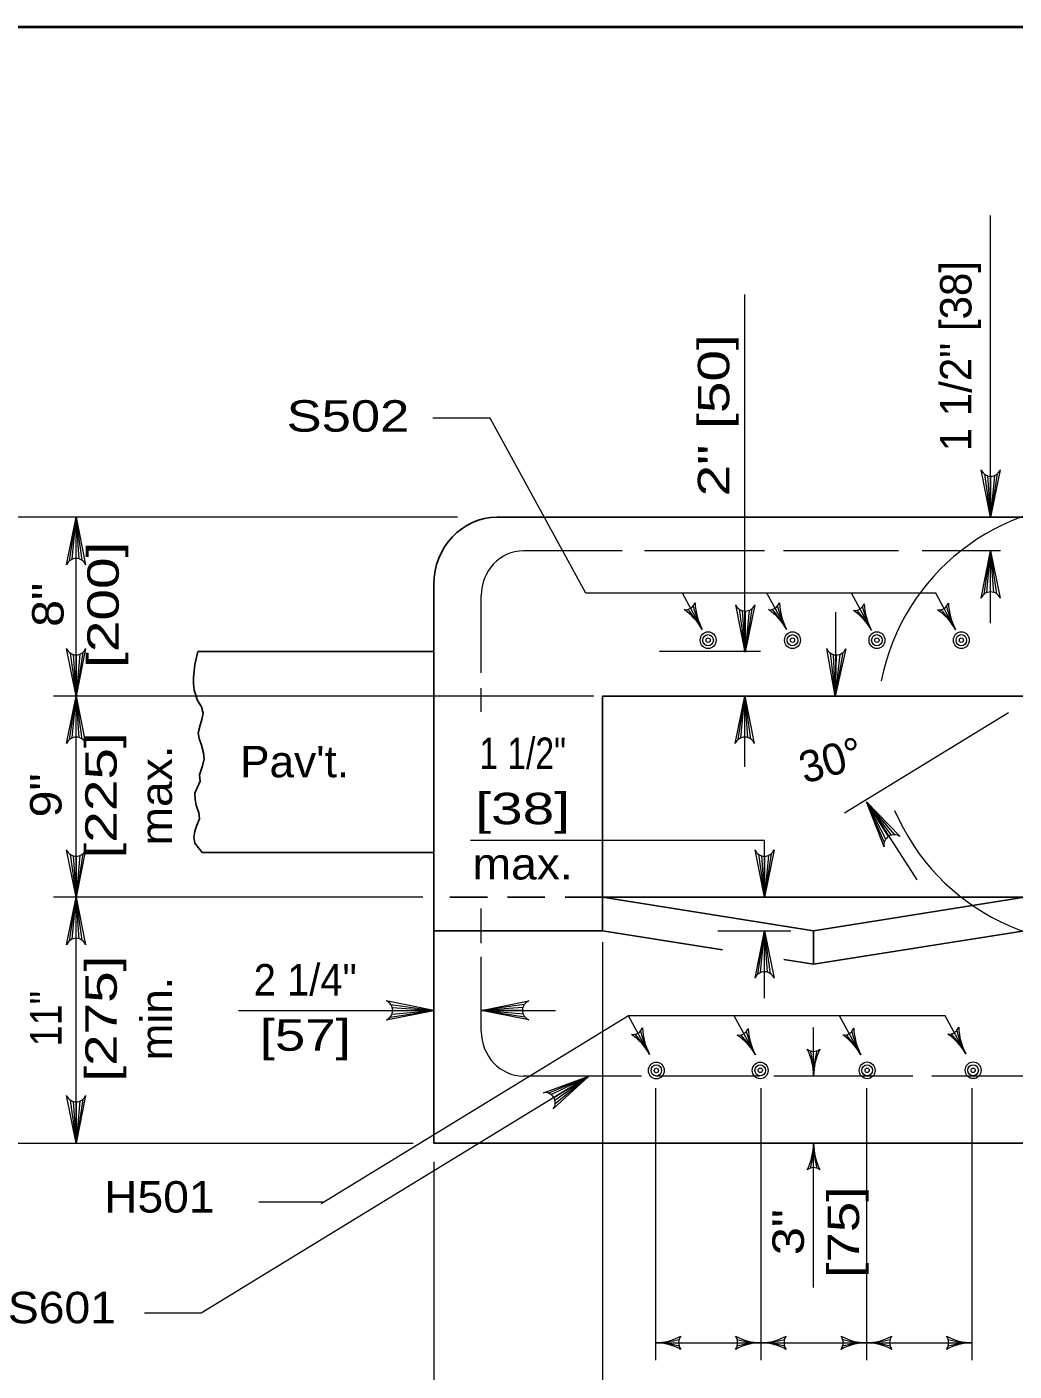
# Model space of a CAD drawing. Extents: x 339.1 to 373.1, y 1412.7 to 1456.7.
# Drawn here: x 355.85 to 360.75, y 1427.58 to 1434.25 of the extents above; entities that cross this region are included whole.
import ezdxf
from ezdxf.enums import TextEntityAlignment as Align

# ---------------------------------------------------------------- set-up
doc = ezdxf.new("R2010")
doc.units = 0
doc.header["$LTSCALE"] = 0.062
doc.linetypes.add('MEDIUM_DASHED', pattern=[4.5, 3, -1.5])
doc.layers.add('1', color=7, linetype='Continuous', lineweight=13)

msp = doc.modelspace()

# ---------------------------------------------------------------- linework, layer by layer
at = {"layer": '1', "lineweight": 25}
for p, q in [((341.0605, 1434.2455), (372.5605, 1434.2455)), ((361.21592, 1431.81325), (358.1795, 1431.81325)), ((357.86533, 1431.14808), (356.69433, 1431.14808)), ((360.85292, 1430.92642), (358.703, 1430.92642)), ((358.703, 1430.92642), (358.703, 1429.98042)), ((357.86533, 1430.15042), (356.71642, 1430.15042)), ((358.703, 1429.98042), (358.703, 1429.76242)), ((358.703, 1429.76242), (357.865, 1429.76242)), ((359.29867, 1429.66783), (358.703, 1429.76242)), ((360.79708, 1429.76242), (359.75008, 1429.59617)), ((359.75008, 1429.59617), (359.75008, 1429.76242)), ((359.75008, 1429.59617), (359.60167, 1429.61975)), ((357.86533, 1428.70933), (361.63475, 1428.70933))]:
    msp.add_line(p, q, dxfattribs=at)
at = {"layer": '1'}
for p, q in [((360.62858, 1431.81325), (360.62858, 1433.30925)), ((359.4085, 1431.14733), (359.4085, 1432.91817)), ((360.59875, 1432.0265), (360.62858, 1431.81325)), ((360.6135, 1432.01925), (360.62858, 1431.81325)), ((360.66158, 1432.029), (360.62858, 1431.81325)), ((360.64775, 1432.02083), (360.62858, 1431.81325)), ((360.62858, 1432.01708), (360.62858, 1431.81325)), ((357.98283, 1431.81325), (355.29933, 1431.81325)), ((356.05758, 1431.59742), (356.09058, 1431.81325)), ((356.07142, 1431.60558), (356.09058, 1431.81325)), ((356.09058, 1431.11825), (356.09058, 1431.81325)), ((356.09058, 1431.60933), (356.09058, 1431.81325)), ((356.10567, 1431.60717), (356.09058, 1431.81325)), ((356.12042, 1431.59992), (356.09058, 1431.81325)), ((358.80058, 1431.64692), (358.31033, 1431.64692)), ((359.5055, 1431.64692), (358.9115, 1431.64692)), ((360.17075, 1431.64692), (359.6005, 1431.64692)), ((360.67767, 1431.64692), (360.2895, 1431.64692)), ((360.59567, 1431.43117), (360.62858, 1431.64692)), ((360.60942, 1431.43933), (360.62858, 1431.64692)), ((360.62858, 1431.28825), (360.62858, 1431.64692)), ((360.62858, 1431.44308), (360.62858, 1431.64692)), ((360.64367, 1431.44092), (360.62858, 1431.64692)), ((360.65842, 1431.43367), (360.62858, 1431.64692)), ((358.10092, 1431.04183), (358.10092, 1431.42525)), ((359.1975, 1431.25675), (359.09958, 1431.43617)), ((359.61633, 1431.25675), (359.51842, 1431.43617)), ((360.03733, 1431.25275), (359.93725, 1431.43617)), ((359.381, 1431.35733), (359.41083, 1431.14408)), ((359.39575, 1431.35017), (359.41083, 1431.14408)), ((359.44383, 1431.35992), (359.41083, 1431.14408)), ((359.43, 1431.35175), (359.41083, 1431.14408)), ((359.41083, 1431.34792), (359.41083, 1431.14408)), ((359.86108, 1430.94608), (359.86108, 1431.34225)), ((356.06075, 1431.13967), (356.09058, 1430.92642)), ((356.0755, 1431.13242), (356.09058, 1430.92642)), ((356.12358, 1431.14217), (356.09058, 1430.92642)), ((356.10975, 1431.134), (356.09058, 1430.92642)), ((356.09058, 1431.13025), (356.09058, 1430.92642)), ((358.98533, 1431.14833), (359.48592, 1431.14833)), ((359.83192, 1431.14042), (359.85775, 1430.92658)), ((359.8465, 1431.13292), (359.85775, 1430.92658)), ((359.89475, 1431.14175), (359.85775, 1430.92658)), ((359.88075, 1431.13383), (359.85775, 1430.92658)), ((359.8615, 1431.13042), (359.85775, 1430.92658)), ((358.65983, 1430.92642), (355.9785, 1430.92642)), ((356.05758, 1430.71058), (356.09058, 1430.92642)), ((356.07142, 1430.71875), (356.09058, 1430.92642)), ((356.09058, 1430.7225), (356.09058, 1430.92642)), ((356.10567, 1430.72033), (356.09058, 1430.92642)), ((356.12042, 1430.71308), (356.09058, 1430.92642)), ((358.10092, 1430.84767), (358.10092, 1430.96633)), ((359.3755, 1430.71058), (359.4085, 1430.92642)), ((359.38933, 1430.71875), (359.4085, 1430.92642)), ((359.4085, 1430.57492), (359.4085, 1430.92642)), ((359.4085, 1430.7225), (359.4085, 1430.92642)), ((359.42358, 1430.72033), (359.4085, 1430.92642)), ((359.43833, 1430.71308), (359.4085, 1430.92642)), ((360.71733, 1430.8435), (359.90292, 1430.34567)), ((360.12233, 1430.23067), (360.01267, 1430.4025)), ((360.10817, 1430.21717), (360.01267, 1430.4025)), ((360.10092, 1430.20283), (360.01267, 1430.4025)), ((360.13625, 1430.23692), (360.01267, 1430.4025)), ((360.15258, 1430.23875), (360.01267, 1430.4025)), ((360.016, 1430.399), (360.262, 1430.0155)), ((359.276, 1430.20975), (358.04725, 1430.20975)), ((359.50642, 1430.20975), (359.276, 1430.20975)), ((359.50642, 1429.92875), (359.50642, 1430.20975)), ((356.06075, 1430.142), (356.09058, 1429.92875)), ((356.0755, 1430.13475), (356.09058, 1429.92875)), ((356.12358, 1430.1445), (356.09058, 1429.92875)), ((356.10975, 1430.13633), (356.09058, 1429.92875)), ((356.09058, 1430.13258), (356.09058, 1429.92875)), ((359.47658, 1430.142), (359.50642, 1429.92875)), ((359.49133, 1430.13475), (359.50642, 1429.92875)), ((359.53942, 1430.1445), (359.50642, 1429.92875)), ((359.52558, 1430.13633), (359.50642, 1429.92875)), ((359.50642, 1430.13258), (359.50642, 1429.92875)), ((357.81142, 1429.92875), (355.9785, 1429.92875)), ((356.05758, 1429.71292), (356.09058, 1429.92875)), ((356.07142, 1429.72108), (356.09058, 1429.92875)), ((356.09058, 1429.72483), (356.09058, 1429.92875)), ((356.10567, 1429.72267), (356.09058, 1429.92875)), ((356.12042, 1429.71542), (356.09058, 1429.92875)), ((358.10092, 1429.70025), (358.10092, 1429.872)), ((359.27425, 1429.76242), (359.63642, 1429.76242)), ((359.47342, 1429.54667), (359.50642, 1429.76242)), ((359.48725, 1429.55483), (359.50642, 1429.76242)), ((359.50642, 1429.42783), (359.50642, 1429.76242)), ((359.50642, 1429.55858), (359.50642, 1429.76242)), ((359.5215, 1429.55633), (359.50642, 1429.76242)), ((359.53625, 1429.54917), (359.50642, 1429.76242)), ((358.703, 1429.706), (358.703, 1427.18717)), ((358.10092, 1429.26358), (358.10092, 1429.63308)), ((357.65208, 1429.39733), (357.86533, 1429.3675)), ((358.31425, 1429.39733), (358.10092, 1429.3675)), ((356.89608, 1429.3675), (357.86533, 1429.3675)), ((357.64958, 1429.3345), (357.86533, 1429.3675)), ((357.65775, 1429.34833), (357.86533, 1429.3675)), ((357.65925, 1429.38258), (357.86533, 1429.3675)), ((357.6615, 1429.3675), (357.86533, 1429.3675)), ((358.307, 1429.38258), (358.10092, 1429.3675)), ((358.10092, 1429.3675), (358.47, 1429.3675)), ((358.30483, 1429.3675), (358.10092, 1429.3675)), ((358.30858, 1429.34833), (358.10092, 1429.3675)), ((358.31675, 1429.3345), (358.10092, 1429.3675)), ((358.93642, 1429.14942), (358.83217, 1429.34033)), ((359.4615, 1429.14642), (359.35575, 1429.34033)), ((359.98483, 1429.14675), (359.87925, 1429.34033)), ((360.50567, 1429.1515), (360.40275, 1429.34033)), ((359.75008, 1429.04192), (359.75008, 1429.28233)), ((358.6345, 1429.04192), (356.71133, 1427.86642)), ((358.89567, 1429.04192), (358.31033, 1429.04192)), ((358.43317, 1428.9575), (358.6345, 1429.04192)), ((358.44733, 1428.95), (358.6345, 1429.04192)), ((358.46058, 1428.93558), (358.6345, 1429.04192)), ((358.46658, 1428.92158), (358.6345, 1429.04192)), ((358.46808, 1428.90517), (358.6345, 1429.04192)), ((359.48167, 1429.04192), (358.96683, 1429.04192)), ((360.24208, 1429.04192), (359.553, 1429.04192)), ((360.86767, 1429.04192), (360.337, 1429.04192)), ((356.06075, 1428.92258), (356.09058, 1428.70933)), ((356.12358, 1428.92517), (356.09058, 1428.70933)), ((358.96475, 1428.98133), (358.96475, 1427.63217)), ((359.48825, 1428.98133), (359.48825, 1427.63217)), ((360.01183, 1428.98133), (360.01183, 1427.63217)), ((360.53533, 1428.98133), (360.53533, 1427.63217)), ((356.0755, 1428.91542), (356.09058, 1428.70933)), ((356.10975, 1428.917), (356.09058, 1428.70933)), ((356.09058, 1428.91317), (356.09058, 1428.70933)), ((355.29933, 1428.70933), (357.76242, 1428.70933)), ((359.75008, 1427.99358), (359.75008, 1428.70933)), ((357.86533, 1428.61708), (357.86533, 1426.47592)), ((357.31917, 1428.41558), (356.99667, 1428.41558)), ((356.71133, 1427.86642), (356.42958, 1427.86642))]:
    msp.add_line(p, q, dxfattribs=at)
at = {"layer": '1', "linetype": 'MEDIUM_DASHED', "lineweight": 25}
msp.add_line((358.703, 1429.92875), (357.86542, 1429.92875), dxfattribs=at)
at = {"layer": '1', "lineweight": 40}
msp.add_lwpolyline([(341.0605, 1434.2455), (372.5605, 1434.2455), (372.5605, 1413.2455), (341.0605, 1413.2455)], close=True, dxfattribs=at)
at = {"layer": '1'}
for points in [[(360.45475, 1431.25533), (360.35608, 1431.43617), (358.619, 1431.43617), (358.145, 1432.30558), (357.86133, 1432.30558)], [(360.67575, 1432.04883), (360.62858, 1431.81325), (360.5815, 1432.04883)], [(356.04342, 1431.57767), (356.09058, 1431.81325), (356.13767, 1431.57767)], [(360.5815, 1431.41133), (360.62858, 1431.64692), (360.67575, 1431.41133)], [(359.45792, 1431.37967), (359.41083, 1431.14408), (359.36375, 1431.37967)], [(356.13767, 1431.162), (356.09058, 1430.92642), (356.04342, 1431.162)], [(356.09058, 1428.70933), (356.09058, 1429.92875), (356.09058, 1430.92642), (356.09058, 1431.17658)], [(359.90925, 1431.16125), (359.85775, 1430.92658), (359.815, 1431.163)], [(356.04342, 1430.69083), (356.09058, 1430.92642), (356.13767, 1430.69083)], [(359.36142, 1430.69083), (359.4085, 1430.92642), (359.45567, 1430.69083)], [(360.09967, 1430.1785), (360.01267, 1430.4025), (360.17908, 1430.22925)], [(356.13767, 1430.16433), (356.09058, 1429.92875), (356.04342, 1430.16433)], [(359.55358, 1430.16433), (359.50642, 1429.92875), (359.45933, 1430.16433)], [(356.04342, 1429.69317), (356.09058, 1429.92875), (356.13767, 1429.69317)], [(359.45933, 1429.52683), (359.50642, 1429.76242), (359.55358, 1429.52683)], [(357.62975, 1429.32033), (357.86533, 1429.3675), (357.62975, 1429.41458)], [(358.3365, 1429.32033), (358.10092, 1429.3675), (358.3365, 1429.41458)], [(360.40275, 1429.34033), (358.83217, 1429.34033), (357.30633, 1428.40767)], [(358.40892, 1428.95925), (358.6345, 1429.04192), (358.45808, 1428.87883)], [(356.13767, 1428.94492), (356.09058, 1428.70933), (356.04342, 1428.94492)], [(358.96475, 1427.71883), (359.48825, 1427.71883), (360.01183, 1427.71883), (360.53567, 1427.71883)]]:
    msp.add_lwpolyline(points, dxfattribs=at)
at = {"layer": '1', "lineweight": 25}
for points in [[(357.86533, 1428.70933), (357.86533, 1430.39267), (357.86533, 1431.48067)], [(356.69433, 1431.14808), (356.67883, 1431.08258), (356.67708, 1431.04958), (356.67358, 1431.02017), (356.67358, 1430.98892), (356.67708, 1430.95583), (356.69275, 1430.90442), (356.71183, 1430.87325), (356.7205, 1430.842), (356.7135, 1430.81075), (356.70658, 1430.78142), (356.69625, 1430.74467), (356.70133, 1430.71533), (356.71183, 1430.68225), (356.72217, 1430.6455), (356.72567, 1430.61433), (356.71708, 1430.58117), (356.70317, 1430.53533), (356.70658, 1430.504), (356.69275, 1430.47467), (356.67883, 1430.44525), (356.68067, 1430.41417), (356.68575, 1430.38475), (356.69967, 1430.348), (356.70317, 1430.31683), (356.68925, 1430.28558), (356.67883, 1430.25617), (356.67542, 1430.22675), (356.67883, 1430.19742), (356.71642, 1430.15042)]]:
    msp.add_lwpolyline(points, dxfattribs=at)
msp.add_lwpolyline([(360.79708, 1429.92875), (358.703, 1429.92875), (359.75008, 1429.76242)], close=True, dxfattribs=at)
at = {"layer": '1'}
for centre, radius, start, end in [((360.62856, 1432.06783), 0.05085, 202.08782, 337.91395), ((361.15655, 1430.78871), 1.09229, 203.13318, 168.75407), ((356.09062, 1431.5586), 0.05085, 22.08782, 157.91395), ((360.62867, 1431.39232), 0.05085, 22.08782, 157.91395), ((359.41078, 1431.3987), 0.05085, 202.08782, 337.91395), ((356.09052, 1431.181), 0.05085, 202.08782, 337.91395), ((359.86243, 1431.18115), 0.05085, 201.01792, 336.84405), ((356.09062, 1430.67178), 0.05085, 22.08782, 157.91395), ((359.40857, 1430.67178), 0.05085, 22.08782, 157.91395), ((360.14966, 1430.18787), 0.05085, 54.6311, 190.45723), ((356.09052, 1430.18333), 0.05085, 202.08782, 337.91395), ((359.50639, 1430.18333), 0.05085, 202.08782, 337.91395), ((356.09062, 1429.67411), 0.05085, 22.08782, 157.91395), ((359.50649, 1429.50782), 0.05085, 22.08782, 157.91395), ((357.61074, 1429.36752), 0.05085, 292.08605, 67.91218), ((358.35555, 1429.36752), 0.05085, 112.08782, 247.91395), ((356.09052, 1428.96395), 0.05085, 202.08782, 337.91395), ((358.4173, 1428.90907), 0.05085, 323.5209, 99.34703)]:
    msp.add_arc(centre, radius, start, end, dxfattribs=at)
at = {"layer": '1', "lineweight": 25}
msp.add_ellipse((358.17947, 1431.48066), major_axis=(0, 0.33256), ratio=0.944544, start_param=6.2831853, end_param=7.8539816, dxfattribs=at)
at = {"layer": '1'}
for centre, major_axis, ratio, start_param, end_param in [((358.31035, 1431.42523), (0, 0.22171), 0.944544, 6.2831853, 7.8539815), ((359.11385, 1431.40989), (0, -0.05499), 0.944544, 6.157414, 7.4564042), ((359.44026, 1431.40168), (0, -0.29516), 0.944544, 4.7567185, 5.2255498), ((359.53267, 1431.40989), (0, -0.05499), 0.944544, 6.157414, 7.4564042), ((359.85908, 1431.40168), (0, -0.29516), 0.944544, 4.7567185, 5.2255498), ((360.37108, 1431.40847), (0, -0.05499), 0.944544, 6.1571807, 7.4561709), ((360.69749, 1431.40018), (0, -0.29516), 0.944544, 4.7564852, 5.2253165), ((358.96146, 1431.11026), (0, 0.28968), 0.944544, 5.2425008, 5.7208574), ((359.07804, 1431.18034), (-0.14057, 0.25475), 0.486077, 4.7419867, 5.1804541), ((359.31946, 1431.32794), (0.1305, -0.2607), 0.484149, 4.3073944, 4.7432566), ((359.38028, 1431.11026), (0, 0.28968), 0.944544, 5.2425008, 5.7208574), ((359.49687, 1431.18034), (-0.14057, 0.25475), 0.486077, 4.7419867, 5.1804541), ((359.73828, 1431.32794), (0.1305, -0.2607), 0.484149, 4.3073944, 4.7432566), ((359.95368, 1431.40589), (0, -0.05499), 0.944544, 6.1575089, 7.4564991), ((359.80131, 1431.10625), (0, 0.28968), 0.944544, 5.2425957, 5.7209523), ((359.91789, 1431.17634), (-0.14059, 0.25473), 0.486081, 4.7419904, 5.1804578), ((360.15929, 1431.32397), (-0.13053, 0.26068), 0.484153, 1.1658059, 1.6016681), ((360.28009, 1431.39771), (0, -0.29516), 0.944544, 4.7568134, 5.2256447), ((360.21862, 1431.10888), (0, 0.28968), 0.944544, 5.2422675, 5.7206241), ((360.33522, 1431.17893), (-0.14052, 0.25478), 0.486066, 4.7419777, 5.1804451), ((360.57667, 1431.32647), (0.13045, -0.26073), 0.484139, 4.3073844, 4.7432465), ((359.26897, 1431.12253), (-0.00568, 0.29509), 0.472393, 4.7873286, 5.1496908), ((359.54775, 1431.12253), (-0.00568, -0.29509), 0.472393, 4.2754323, 4.6374494), ((358.31035, 1429.2636), (0, 0.22171), 0.944544, 1.5707963, 3.1415926), ((358.85268, 1429.30256), (0, -0.05499), 0.944544, 6.1576386, 7.4566288), ((359.05831, 1429.22066), (0.13056, -0.26067), 0.484159, 4.3074041, 4.7432663), ((359.17909, 1429.29442), (0, -0.29516), 0.944544, 4.7569431, 5.2257744), ((359.37782, 1429.29959), (0, -0.05499), 0.944544, 6.1573809, 7.4563711), ((359.58342, 1429.21764), (0.1305, -0.2607), 0.484148, 4.307393, 4.7432552), ((359.70423, 1429.29136), (0, -0.29516), 0.944544, 4.7566854, 5.2255167), ((359.90115, 1429.29993), (0, -0.05499), 0.944544, 6.157266, 7.4562562), ((360.10675, 1429.21795), (0.13047, -0.26072), 0.484143, 4.307388, 4.7432502), ((360.22756, 1429.29167), (0, -0.29516), 0.944544, 4.7565705, 5.2254018), ((360.42207, 1429.3047), (0, -0.05499), 0.944544, 6.1571888, 7.456179), ((360.62766, 1429.22271), (0.13045, -0.26073), 0.484139, 4.3073847, 4.7432469), ((360.74848, 1429.29641), (0, -0.29516), 0.944544, 4.7564933, 5.2253246), ((358.70035, 1429.0029), (0, 0.28968), 0.944544, 5.2427255, 5.721082), ((358.81693, 1429.073), (-0.14062, 0.25472), 0.486087, 4.7419954, 5.1804629), ((359.22542, 1428.99997), (0, 0.28968), 0.944544, 5.2424678, 5.7208244), ((359.342, 1429.07004), (-0.14056, 0.25475), 0.486075, 4.7419854, 5.1804529), ((359.74872, 1429.00033), (0, 0.28968), 0.944544, 5.2423528, 5.7207094), ((359.86531, 1429.07039), (0.14054, -0.25477), 0.48607, 1.6003883, 2.0388558), ((360.26962, 1429.00511), (0, 0.28968), 0.944544, 5.2422756, 5.7206322), ((360.38622, 1429.07516), (-0.14052, 0.25478), 0.486066, 4.741978, 5.1804454), ((359.74994, 1429.21882), (0, -0.05499), 0.944544, 5.6336903, 6.9326805), ((359.47644, 1429.04004), (0, 0.28968), 0.944544, 4.718777, 5.1971336), ((359.6105, 1429.039), (-0.00568, 0.29509), 0.472393, 4.7112233, 5.1496908), ((359.88928, 1429.039), (-0.00568, -0.29509), 0.472393, 4.2754323, 4.7112945), ((360.02872, 1429.03889), (0, 0.29516), 0.944544, 1.0914021, 1.5602334), ((359.47137, 1428.71234), (0, -0.29516), 0.944544, 1.0914021, 1.5602334), ((359.61082, 1428.71223), (0.00568, 0.29509), 0.472393, 4.2754323, 4.7112945), ((360.02366, 1428.71119), (0, -0.28968), 0.944544, 4.718777, 5.1971336), ((359.88959, 1428.71223), (0.00568, -0.29509), 0.472393, 4.7112233, 5.1496908), ((359.75015, 1428.53241), (0, 0.05499), 0.944544, 5.6336903, 6.9326805), ((358.96202, 1427.86656), (0.27871, 0.0065), 0.529437, 4.7079837, 5.1464512), ((358.96301, 1428.0085), (0, -0.28968), 0.944544, 0.006388, 0.4847446), ((359.13187, 1427.71893), (0, -0.05499), 0.944544, 4.062894, 5.3618842), ((359.49112, 1428.01386), (0, -0.29516), 0.944544, 5.8037911, 6.2726224), ((359.32117, 1427.71871), (0, 0.05499), 0.944544, 4.062894, 5.3618842), ((359.49102, 1427.86623), (0.27871, -0.0065), 0.529437, 4.2786719, 4.7145341), ((359.48555, 1427.86656), (0.27871, 0.0065), 0.529437, 4.7079837, 5.1464512), ((359.48654, 1428.0085), (0, -0.28968), 0.944544, 0.006388, 0.4847446), ((359.6554, 1427.71893), (0, -0.05499), 0.944544, 4.062894, 5.3618842), ((360.01465, 1428.01386), (0, -0.29516), 0.944544, 5.8037911, 6.2726224), ((359.8447, 1427.71871), (0, 0.05499), 0.944544, 4.062894, 5.3618842), ((360.01455, 1427.86623), (0.27871, -0.0065), 0.529437, 4.2786719, 4.7145341), ((360.00908, 1427.86656), (0.27871, 0.0065), 0.529437, 4.7079837, 5.1464512), ((360.01006, 1428.0085), (0, -0.28968), 0.944544, 0.006388, 0.4847446), ((360.17893, 1427.71893), (0, -0.05499), 0.944544, 4.062894, 5.3618842), ((360.53849, 1428.01386), (0, -0.29516), 0.944544, 5.8037911, 6.2726224), ((360.36854, 1427.71871), (0, 0.05499), 0.944544, 4.062894, 5.3618842), ((360.53839, 1427.86623), (0.27871, -0.0065), 0.529437, 4.2786719, 4.7145341), ((358.96202, 1427.57142), (-0.27871, 0.0065), 0.529437, 4.2786719, 4.7145341), ((358.96192, 1427.42379), (0, 0.29516), 0.944544, 5.8037911, 6.2726224), ((359.49003, 1427.42915), (0, 0.28968), 0.944544, 0.006388, 0.4847446), ((359.49102, 1427.57108), (-0.27871, -0.0065), 0.529437, 4.7079837, 5.1464512), ((359.48544, 1427.42379), (0, 0.29516), 0.944544, 5.8037911, 6.2726224), ((359.48555, 1427.57142), (-0.27871, 0.0065), 0.529437, 4.2786719, 4.7145341), ((360.01356, 1427.42915), (0, 0.28968), 0.944544, 0.006388, 0.4847446), ((360.01455, 1427.57108), (-0.27871, -0.0065), 0.529437, 4.7079837, 5.1464512), ((360.00897, 1427.42379), (0, 0.29516), 0.944544, 5.8037911, 6.2726224), ((360.00908, 1427.57142), (-0.27871, 0.0065), 0.529437, 4.2786719, 4.7145341), ((360.5374, 1427.42915), (0, 0.28968), 0.944544, 0.006388, 0.4847446), ((360.53839, 1427.57108), (-0.27871, -0.0065), 0.529437, 4.7079837, 5.1464512)]:
    msp.add_ellipse(centre, major_axis=major_axis, ratio=ratio, start_param=start_param, end_param=end_param, dxfattribs=at)
for centre, major_axis in [((359.22652, 1431.20352), (0, 0.04157)), ((359.22652, 1431.20352), (0, -0.02771)), ((359.22652, 1431.20352), (0, 0.01109)), ((359.64534, 1431.20352), (0, 0.04157)), ((359.64534, 1431.20352), (0, -0.02771)), ((359.64534, 1431.20352), (0, 0.01109)), ((360.06416, 1431.20352), (0, 0.04157)), ((360.06416, 1431.20352), (0, -0.02771)), ((360.06416, 1431.20352), (0, 0.01109)), ((360.48299, 1431.20352), (0, 0.04157)), ((360.48299, 1431.20352), (0, -0.02771)), ((360.48299, 1431.20352), (0, 0.01109)), ((358.96968, 1429.06939), (0, 0.04157)), ((358.96968, 1429.06939), (0, 0.02771)), ((358.96968, 1429.06939), (0, 0.01109)), ((359.48514, 1429.06983), (0, 0.04157)), ((359.48514, 1429.06983), (0, 0.02771)), ((359.48514, 1429.06983), (0, 0.01109)), ((360.01569, 1429.06994), (0, 0.04157)), ((360.01569, 1429.06994), (0, 0.02771)), ((360.01569, 1429.06994), (0, 0.01109)), ((360.54152, 1429.07038), (0, 0.04157)), ((360.54152, 1429.07038), (0, 0.02771)), ((360.54152, 1429.07038), (0, 0.01109))]:
    msp.add_ellipse(centre, major_axis=major_axis, ratio=0.944544, dxfattribs=at)

# ---------------------------------------------------------------- texts
for s, rotation, p in [('1 1/2" [38]', 90, (360.53333, 1432.1405)), ('30°', 15.838, (359.70483, 1430.491))]:
    msp.add_text(s, height=0.156, rotation=rotation, dxfattribs=at).set_placement(p)
at = {"layer": '1', "width": 1.35}
msp.add_text('2" [50]', height=0.156, rotation=90, dxfattribs=at).set_placement((359.33158, 1431.91667))
at = {"layer": '1'}
for s, width, p in [('S502', 1.25, (357.13492, 1432.23783)), ("Pav't.", 1.05, (356.90417, 1430.5235)), ('H501', 1.1, (356.22925, 1428.36467)), ('S601', 1.1, (355.752, 1427.81567))]:
    msp.add_text(s, height=0.156, dxfattribs=dict(at, width=width)).set_placement(p)
for s, width, p in [('[200]', 1.35, (356.30208, 1431.37904)), ('8"', 1.15, (356.02808, 1431.37896)), ('[225]', 1.35, (356.29192, 1430.43379)), ('max.', 1.1, (356.56592, 1430.43371)), ('9"', 1.15, (356.01792, 1430.43379)), ('[275]', 1.35, (356.29233, 1429.32646)), ('11"', 0.9, (356.01833, 1429.32642)), ('min.', 1.05, (356.56633, 1429.32637)), ('[75]', 1.3, (359.97575, 1428.26758)), ('3"', 1.2, (359.70175, 1428.2675))]:
    msp.add_text(s, height=0.156, rotation=90, dxfattribs=dict(at, width=width)).set_placement(p, align=Align.CENTER)
for s, width, p in [('1 1/2"', 0.8, (358.30625, 1430.56475)), ('[38]', 1.35, (358.30621, 1430.29075)), ('max.', 1.1, (358.30629, 1430.01675)), ('2 1/4"', 0.95, (357.22742, 1429.44125)), ('[57]', 1.3, (357.2275, 1429.16725))]:
    msp.add_text(s, height=0.156, dxfattribs=dict(at, width=width)).set_placement(p, align=Align.CENTER)

doc.saveas('drawing.dxf')
